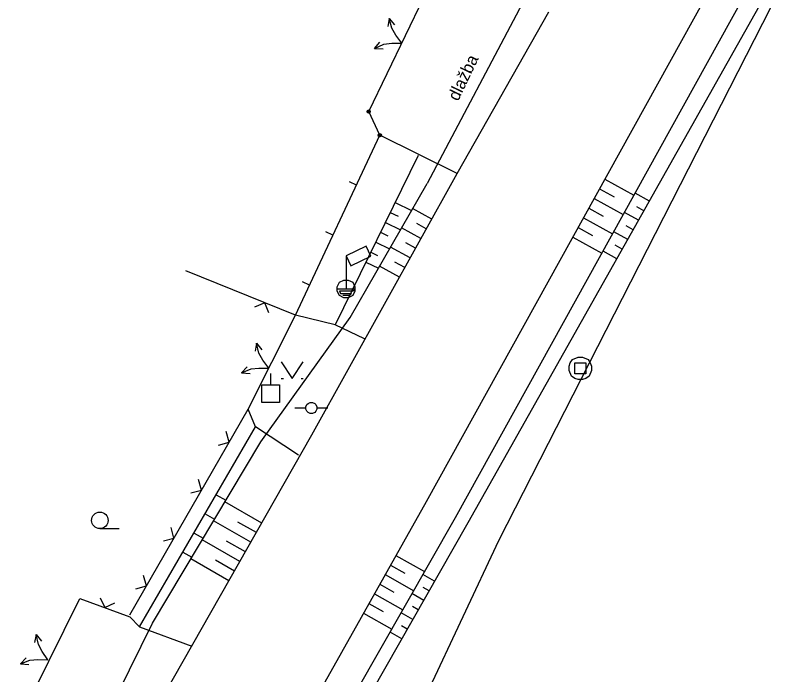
# Model space of a CAD drawing. Extents: x -559554 to -559082, y -1075950 to -1075150.
# Drawn here: x -559442.91 to -559408.73, y -1075772.99 to -1075743.16 of the extents above; entities that cross this region are included whole.
import ezdxf

# ---------------------------------------------------------------- set-up
doc = ezdxf.new("R2010")
doc.units = 0
doc.layers.add('kl', color=7, linetype='Continuous')

msp = doc.modelspace()

# ---------------------------------------------------------------- linework, layer by layer
at = {"layer": 'kl'}
for p, q in [((-559426.92, -1075747.52), (-559423.93, -1075741.33)), ((-559411.156, -1075741.393), (-559424.321, -1075765.158)), ((-559419.48, -1075741.7), (-559424.28, -1075750.77)), ((-559422.993, -1075765.867), (-559409.789, -1075742.037)), ((-559422.428, -1075766.103), (-559409.112, -1075742.5)), ((-559422.92, -1075750.32), (-559418.77, -1075743.01)), ((-559408.734, -1075742.801), (-559421.047, -1075766.927)), ((-559425.998, -1075743.312), (-559426.06, -1075743.671)), ((-559425.88, -1075743.758), (-559425.998, -1075743.312)), ((-559425.998, -1075743.312), (-559425.748, -1075743.599)), ((-559425.697, -1075744.068), (-559425.88, -1075743.758)), ((-559425.423, -1075744.422), (-559425.697, -1075744.068)), ((-559426.65, -1075744.663), (-559426.408, -1075744.391)), ((-559426.228, -1075744.478), (-559425.871, -1075744.428)), ((-559425.871, -1075744.428), (-559425.423, -1075744.422)), ((-559426.65, -1075744.663), (-559426.228, -1075744.478)), ((-559426.65, -1075744.663), (-559426.27, -1075744.68)), ((-559426.975, -1075747.52), (-559426.964, -1075747.498)), ((-559426.885, -1075747.564), (-559426.975, -1075747.52)), ((-559426.964, -1075747.498), (-559426.874, -1075747.541)), ((-559426.953, -1075747.476), (-559426.92, -1075747.464)), ((-559426.863, -1075747.519), (-559426.953, -1075747.476)), ((-559426.92, -1075747.464), (-559426.875, -1075747.486)), ((-559426.42, -1075748.59), (-559426.92, -1075747.52)), ((-559426.874, -1075747.541), (-559426.863, -1075747.519)), ((-559426.964, -1075747.554), (-559426.918, -1075747.576)), ((-559426.918, -1075747.576), (-559426.885, -1075747.564)), ((-559426.475, -1075748.59), (-559426.464, -1075748.568)), ((-559426.464, -1075748.568), (-559426.374, -1075748.611)), ((-559426.453, -1075748.546), (-559426.42, -1075748.534)), ((-559426.363, -1075748.589), (-559426.453, -1075748.546)), ((-559426.42, -1075748.534), (-559426.375, -1075748.556)), ((-559430.23, -1075756.73), (-559426.42, -1075748.59)), ((-559426.385, -1075748.634), (-559426.475, -1075748.59)), ((-559426.464, -1075748.624), (-559426.418, -1075748.646)), ((-559422.92, -1075750.32), (-559426.42, -1075748.59)), ((-559426.418, -1075748.646), (-559426.385, -1075748.634)), ((-559426.374, -1075748.611), (-559426.363, -1075748.589)), ((-559424.68, -1075749.51), (-559428.44, -1075757.17)), ((-559429.483, -1075762.136), (-559422.92, -1075750.32)), ((-559416.242, -1075750.575), (-559414.924, -1075751.305)), ((-559427.474, -1075750.842), (-559427.791, -1075750.694)), ((-559427.76, -1075756.83), (-559424.28, -1075750.77)), ((-559416.484, -1075751.012), (-559415.825, -1075751.377)), ((-559414.226, -1075751.566), (-559414.868, -1075751.204)), ((-559425.722, -1075751.634), (-559424.984, -1075751.996)), ((-559416.727, -1075751.449), (-559415.409, -1075752.179)), ((-559424.07, -1075752.391), (-559424.935, -1075751.911)), ((-559416.969, -1075751.887), (-559416.31, -1075752.252)), ((-559414.472, -1075752.002), (-559414.791, -1075751.821)), ((-559425.942, -1075752.082), (-559425.588, -1075752.257)), ((-559417.211, -1075752.324), (-559415.894, -1075753.054)), ((-559414.718, -1075752.437), (-559415.353, -1075752.079)), ((-559426.163, -1075752.531), (-559425.483, -1075752.865)), ((-559424.313, -1075752.828), (-559424.749, -1075752.586)), ((-559428.534, -1075753.107), (-559428.851, -1075752.958)), ((-559426.383, -1075752.98), (-559426.058, -1075753.14)), ((-559424.556, -1075753.265), (-559425.433, -1075752.778)), ((-559417.453, -1075752.762), (-559416.795, -1075753.126)), ((-559415.209, -1075753.308), (-559415.838, -1075752.953)), ((-559414.964, -1075752.873), (-559415.279, -1075752.694)), ((-559417.696, -1075753.199), (-559416.378, -1075753.929)), ((-559427.037, -1075753.609), (-559427.94, -1075754.04)), ((-559426.822, -1075754.061), (-559427.037, -1075753.609)), ((-559426.603, -1075753.429), (-559425.982, -1075753.734)), ((-559425.041, -1075754.14), (-559425.931, -1075753.645)), ((-559424.799, -1075753.703), (-559425.24, -1075753.457)), ((-559415.455, -1075753.743), (-559415.768, -1075753.567)), ((-559426.824, -1075753.878), (-559426.528, -1075754.023)), ((-559415.701, -1075754.179), (-559416.323, -1075753.828)), ((-559427.94, -1075754.04), (-559427.94, -1075755.54)), ((-559427.94, -1075754.04), (-559427.725, -1075754.491)), ((-559427.725, -1075754.491), (-559426.822, -1075754.061)), ((-559427.044, -1075754.327), (-559426.481, -1075754.603)), ((-559425.284, -1075754.577), (-559425.732, -1075754.328)), ((-559430.23, -1075756.73), (-559435.184, -1075754.717)), ((-559425.527, -1075755.014), (-559426.429, -1075754.513)), ((-559429.594, -1075755.371), (-559429.911, -1075755.223)), ((-559428.34, -1075755.44), (-559428.24, -1075755.24)), ((-559428.24, -1075755.24), (-559428.04, -1075755.14)), ((-559428.04, -1075755.14), (-559427.84, -1075755.14)), ((-559427.84, -1075755.14), (-559427.64, -1075755.24)), ((-559427.64, -1075755.24), (-559427.54, -1075755.44)), ((-559428.34, -1075755.64), (-559428.34, -1075755.44)), ((-559428.34, -1075755.54), (-559427.54, -1075755.54)), ((-559428.24, -1075755.84), (-559428.34, -1075755.64)), ((-559427.64, -1075755.64), (-559428.24, -1075755.64)), ((-559428.24, -1075755.64), (-559428.19, -1075755.74)), ((-559428.19, -1075755.74), (-559427.69, -1075755.74)), ((-559427.69, -1075755.74), (-559427.79, -1075755.84)), ((-559427.54, -1075755.54), (-559427.64, -1075755.64)), ((-559427.54, -1075755.64), (-559427.64, -1075755.84)), ((-559427.54, -1075755.44), (-559427.54, -1075755.64)), ((-559428.04, -1075755.94), (-559428.24, -1075755.84)), ((-559427.79, -1075755.84), (-559428.09, -1075755.84)), ((-559427.84, -1075755.94), (-559428.04, -1075755.94)), ((-559427.64, -1075755.84), (-559427.84, -1075755.94)), ((-559431.619, -1075756.165), (-559432.075, -1075756.357)), ((-559431.427, -1075756.621), (-559431.619, -1075756.165)), ((-559432.37, -1075760.97), (-559430.23, -1075756.73)), ((-559428.44, -1075757.17), (-559430.23, -1075756.73)), ((-559431.8, -1075762.45), (-559427.76, -1075756.83)), ((-559427.11, -1075757.8), (-559428.44, -1075757.17)), ((-559431.99, -1075757.997), (-559432.058, -1075758.355)), ((-559431.879, -1075758.445), (-559431.99, -1075757.997)), ((-559431.99, -1075757.997), (-559431.745, -1075758.289)), ((-559431.702, -1075758.759), (-559431.879, -1075758.445)), ((-559431.435, -1075759.117), (-559431.702, -1075758.759)), ((-559417.802, -1075758.882), (-559417.702, -1075758.732)), ((-559417.702, -1075758.732), (-559417.452, -1075758.632)), ((-559417.452, -1075758.632), (-559417.252, -1075758.632)), ((-559417.252, -1075758.632), (-559417.002, -1075758.732)), ((-559417.002, -1075758.732), (-559416.902, -1075758.882)), ((-559432.665, -1075759.336), (-559432.418, -1075759.069)), ((-559432.665, -1075759.336), (-559432.24, -1075759.159)), ((-559432.24, -1075759.159), (-559431.882, -1075759.116)), ((-559431.882, -1075759.116), (-559431.435, -1075759.117)), ((-559430.876, -1075758.84), (-559430.376, -1075759.59)), ((-559430.376, -1075759.59), (-559429.876, -1075758.84)), ((-559417.852, -1075759.032), (-559417.802, -1075758.882)), ((-559417.852, -1075759.232), (-559417.852, -1075759.032)), ((-559417.602, -1075758.882), (-559417.102, -1075758.882)), ((-559417.602, -1075759.382), (-559417.602, -1075758.882)), ((-559417.102, -1075758.882), (-559417.102, -1075759.382)), ((-559416.902, -1075758.882), (-559416.852, -1075759.032)), ((-559416.852, -1075759.032), (-559416.852, -1075759.232)), ((-559432.665, -1075759.336), (-559432.285, -1075759.36)), ((-559431.35, -1075759.87), (-559431.35, -1075759.37)), ((-559417.752, -1075759.482), (-559417.852, -1075759.232)), ((-559417.602, -1075759.582), (-559417.752, -1075759.482)), ((-559417.102, -1075759.382), (-559417.602, -1075759.382)), ((-559416.952, -1075759.482), (-559417.102, -1075759.582)), ((-559416.852, -1075759.232), (-559416.952, -1075759.482)), ((-559430.876, -1075759.59), (-559430.776, -1075759.59)), ((-559429.976, -1075759.59), (-559429.876, -1075759.59)), ((-559417.452, -1075759.632), (-559417.602, -1075759.582)), ((-559417.252, -1075759.632), (-559417.452, -1075759.632)), ((-559417.102, -1075759.582), (-559417.252, -1075759.632)), ((-559431.75, -1075759.87), (-559430.95, -1075759.87)), ((-559431.75, -1075760.67), (-559431.75, -1075759.87)), ((-559430.95, -1075759.87), (-559430.95, -1075760.67)), ((-559430.95, -1075760.67), (-559431.75, -1075760.67)), ((-559429.76, -1075760.87), (-559429.71, -1075760.77)), ((-559429.76, -1075760.97), (-559429.76, -1075760.87)), ((-559429.71, -1075760.77), (-559429.66, -1075760.72)), ((-559429.66, -1075760.72), (-559429.56, -1075760.67)), ((-559429.56, -1075760.67), (-559429.46, -1075760.67)), ((-559429.46, -1075760.67), (-559429.36, -1075760.72)), ((-559429.36, -1075760.72), (-559429.31, -1075760.77)), ((-559429.31, -1075760.77), (-559429.26, -1075760.87)), ((-559429.26, -1075760.87), (-559429.26, -1075760.97)), ((-559437.72, -1075770.27), (-559432.37, -1075760.97)), ((-559432.03, -1075761.78), (-559432.37, -1075760.97)), ((-559430.26, -1075760.92), (-559429.76, -1075760.92)), ((-559429.71, -1075761.07), (-559429.76, -1075760.97)), ((-559429.66, -1075761.12), (-559429.71, -1075761.07)), ((-559429.56, -1075761.17), (-559429.66, -1075761.12)), ((-559429.46, -1075761.17), (-559429.56, -1075761.17)), ((-559429.36, -1075761.12), (-559429.46, -1075761.17)), ((-559429.31, -1075761.07), (-559429.36, -1075761.12)), ((-559429.26, -1075760.97), (-559429.31, -1075761.07)), ((-559429.26, -1075760.92), (-559428.76, -1075760.92)), ((-559437.28, -1075770.82), (-559432.03, -1075761.78)), ((-559430.09, -1075763.05), (-559432.03, -1075761.78)), ((-559442.906, -1075785.721), (-559429.483, -1075762.136)), ((-559433.232, -1075762.468), (-559433.361, -1075761.99)), ((-559436.7, -1075770.65), (-559431.8, -1075762.45)), ((-559433.71, -1075762.597), (-559433.232, -1075762.468)), ((-559434.478, -1075764.635), (-559434.607, -1075764.157)), ((-559434.956, -1075764.764), (-559434.478, -1075764.635)), ((-559433.811, -1075764.847), (-559433.381, -1075765.096)), ((-559424.321, -1075765.158), (-559437.486, -1075788.593)), ((-559431.752, -1075766.123), (-559433.425, -1075765.17)), ((-559436.305, -1075789.206), (-559422.993, -1075765.867)), ((-559434.313, -1075765.712), (-559433.894, -1075765.955)), ((-559435.725, -1075766.802), (-559435.854, -1075766.324)), ((-559435.747, -1075789.474), (-559422.428, -1075766.103)), ((-559432.247, -1075766.992), (-559433.938, -1075766.029)), ((-559431.999, -1075766.557), (-559432.841, -1075766.078)), ((-559439.073, -1075766.376), (-559438.198, -1075766.376)), ((-559434.815, -1075766.576), (-559434.407, -1075766.813)), ((-559436.203, -1075766.931), (-559435.725, -1075766.802)), ((-559432.741, -1075767.861), (-559434.452, -1075766.888)), ((-559432.494, -1075767.426), (-559433.345, -1075766.942)), ((-559421.047, -1075766.927), (-559429.623, -1075785.177)), ((-559435.318, -1075767.441), (-559434.92, -1075767.672)), ((-559425.685, -1075767.586), (-559424.389, -1075768.314)), ((-559433.236, -1075768.73), (-559434.965, -1075767.746)), ((-559432.989, -1075768.295), (-559433.848, -1075767.806)), ((-559425.93, -1075768.022), (-559425.283, -1075768.385)), ((-559436.972, -1075768.969), (-559437.1, -1075768.491)), ((-559426.174, -1075768.458), (-559424.884, -1075769.182)), ((-559423.937, -1075768.75), (-559424.466, -1075768.449)), ((-559437.449, -1075769.098), (-559436.972, -1075768.969)), ((-559426.419, -1075768.894), (-559425.776, -1075769.255)), ((-559424.184, -1075769.184), (-559424.449, -1075769.034)), ((-559426.664, -1075769.33), (-559425.38, -1075770.051)), ((-559424.432, -1075769.619), (-559424.961, -1075769.317)), ((-559442.27, -1075774.15), (-559439.978, -1075769.537)), ((-559439.978, -1075769.537), (-559437.72, -1075770.36)), ((-559439.058, -1075769.5), (-559438.849, -1075769.948)), ((-559438.849, -1075769.948), (-559438.4, -1075769.739)), ((-559426.909, -1075769.765), (-559426.268, -1075770.125)), ((-559424.679, -1075770.053), (-559424.944, -1075769.902)), ((-559437.28, -1075770.82), (-559437.72, -1075770.36)), ((-559427.154, -1075770.201), (-559425.875, -1075770.92)), ((-559424.927, -1075770.488), (-559425.457, -1075770.186)), ((-559440.48, -1075778.3), (-559436.7, -1075770.65)), ((-559425.174, -1075770.922), (-559425.439, -1075770.771)), ((-559437.28, -1075770.82), (-559434.921, -1075771.691)), ((-559425.422, -1075771.357), (-559425.952, -1075771.054)), ((-559441.947, -1075771.165), (-559442.027, -1075771.52)), ((-559441.851, -1075771.616), (-559441.947, -1075771.165)), ((-559441.947, -1075771.165), (-559441.711, -1075771.464)), ((-559441.683, -1075771.935), (-559441.851, -1075771.616)), ((-559441.427, -1075772.302), (-559441.683, -1075771.935)), ((-559442.664, -1075772.482), (-559442.409, -1075772.223)), ((-559442.664, -1075772.482), (-559442.233, -1075772.318)), ((-559442.664, -1075772.482), (-559442.285, -1075772.518)), ((-559442.233, -1075772.318), (-559441.874, -1075772.286)), ((-559441.874, -1075772.286), (-559441.427, -1075772.302))]:
    msp.add_line(p, q, dxfattribs=at)
for centre, radius in [((-559426.92, -1075747.52), 0.075), ((-559426.42, -1075748.59), 0.075), ((-559439.074, -1075766.002), 0.375)]:
    msp.add_circle(centre, radius, dxfattribs=at)

# ---------------------------------------------------------------- texts
msp.add_text('dlažba', height=0.5525, rotation=64.4557, dxfattribs=at).set_placement((-559422.876, -1075747.082))

doc.saveas('drawing.dxf')
